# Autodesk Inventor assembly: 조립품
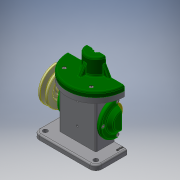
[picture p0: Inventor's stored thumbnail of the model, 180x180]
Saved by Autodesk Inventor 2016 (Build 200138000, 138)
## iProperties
Created: 2021-05
Part Number: 조립품
Material: 일반
Document SubType Name: Assembly
Designer: CAD16
Author: CAD16
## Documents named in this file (19)
- C:\Users\CAD16\Desktop\710506v1012\조립품.iam
- C:\Users\CAD16\Desktop\710506v1012\본체.ipt
- C:\Users\CAD16\Desktop\710506v1012\덮개.ipt
- C:\Users\CAD16\Desktop\710506v1012\E-링.ipt
- C:\Users\CAD16\Desktop\710506v1012\슬라이더.ipt
- C:\Users\CAD16\Desktop\710506v1012\클레비스 핀 6 x 22.ipt
- 클레비스 핀 6 x 22.ipt
- C:\Users\CAD16\Desktop\710506v1012\편심축.ipt
- C:\Users\CAD16\Desktop\710506v1012\베어링 17 x 40 x 12.ipt
- C:\Users\CAD16\Desktop\710506v1012\뒤커버.ipt
- C:\Users\CAD16\Desktop\710506v1012\앞커버.ipt
- C:\Users\CAD16\Desktop\710506v1012\오일 실 17 30 8.ipt
- C:\Users\CAD16\Desktop\710506v1012\V-벨트풀리.ipt
- C:\Users\CAD16\Desktop\710506v1012\와셔 4x16.ipt
- C:\Users\CAD16\Desktop\710506v1012\키 4 x 4 x 12.ipt
- C:\Users\CAD16\Desktop\710506v1012\볼트 M4 x 10.ipt
- C:\Users\CAD16\Desktop\710506v1012\볼트 M4 x 12.ipt
- 볼트 M4 x 12.ipt
- C:\Users\CAD16\Desktop\710506v1012\링크.ipt
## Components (2 placed, 2 different names)
1. E-링:1
2. V-벨트풀리:1
